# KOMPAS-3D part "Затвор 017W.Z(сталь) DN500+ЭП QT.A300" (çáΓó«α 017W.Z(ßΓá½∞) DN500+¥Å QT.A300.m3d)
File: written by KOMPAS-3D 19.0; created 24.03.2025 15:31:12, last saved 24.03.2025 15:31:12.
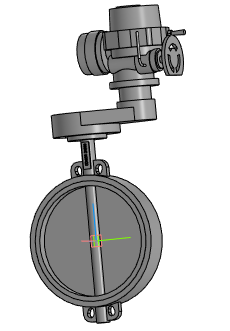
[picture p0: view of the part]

Document properties: Полное имя файла: Затвор 017W.Z(сталь) DN500+ЭП QT.A300.a3d

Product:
- Part/product: Затвор 017W.Z(сталь) DN500+ЭП QT.A300
    Масса: 361.861

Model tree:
1. Операция без истории:1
